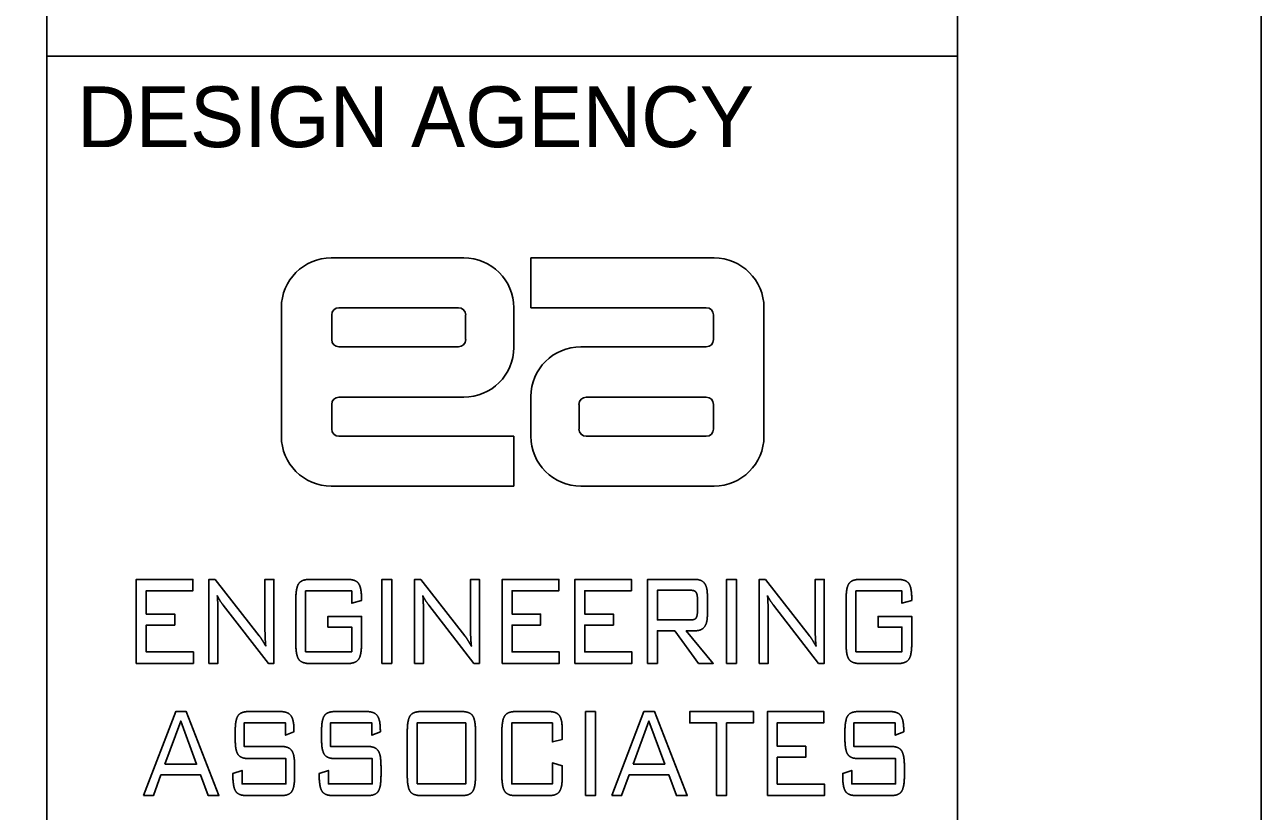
# Model space of a CAD drawing. Extents: x 0 to 34, y 0 to 22.
# Drawn here: x 31.964 to 34, y 3.757 to 5.052 of the extents above; entities that cross this region are included whole.
import ezdxf

# ---------------------------------------------------------------- set-up
doc = ezdxf.new("R2010")
doc.units = 0
for name, color, linetype in [('SH_Border', 7, 'Continuous'), ('SH_Cut_Line', 7, 'Continuous'), ('SH_Data', 7, 'Continuous'), ('TX_X_20', 7, 'Continuous')]:
    doc.layers.add(name, color=color, linetype=linetype)

msp = doc.modelspace()

# ---------------------------------------------------------------- linework, layer by layer
at = {"layer": 'SH_Border'}
for p, q in [((32, 0.5), (32, 21.5)), ((32, 5), (33.5, 5))]:
    msp.add_line(p, q, dxfattribs=at)
msp.add_lwpolyline([(1.5, 21.5), (33.5, 21.5), (33.5, 0.5), (1.5, 0.5)], close=True, dxfattribs=at)
at = {"layer": 'SH_Cut_Line'}
msp.add_lwpolyline([(0, 0), (34, 0), (34, 22), (0, 22)], close=True, dxfattribs=at)
at = {"layer": 'SH_Data'}
msp.add_line((32.75, 4), (32.75, 4), dxfattribs=at)
at = {"layer": 'TX_X_20'}
for p, q in [((32.6869, 4.6677), (32.4684, 4.6677)), ((32.4684, 4.6677), (32.6869, 4.6677)), ((32.7974, 4.6677), (33.0989, 4.6677)), ((32.7974, 4.5856), (32.7974, 4.6677)), ((32.3863, 4.5856), (32.3863, 4.3741)), ((32.3863, 4.3741), (32.3863, 4.5856)), ((32.4812, 4.5856), (32.678, 4.5856)), ((32.678, 4.5856), (32.4812, 4.5856)), ((32.7689, 4.5204), (32.7689, 4.5856)), ((32.7689, 4.5856), (32.7689, 4.5204)), ((33.086, 4.5856), (32.7974, 4.5856)), ((33.1809, 4.3741), (33.1809, 4.5856)), ((33.1809, 4.5856), (33.1809, 4.3741)), ((32.4694, 4.5332), (32.4694, 4.5738)), ((32.4694, 4.5738), (32.4694, 4.5332)), ((32.6898, 4.5738), (32.6898, 4.5332)), ((32.6898, 4.5332), (32.6898, 4.5738)), ((33.0979, 4.5738), (33.0979, 4.5332)), ((33.0979, 4.5332), (33.0979, 4.5738)), ((32.678, 4.5214), (32.4812, 4.5214)), ((32.4812, 4.5214), (32.678, 4.5214)), ((33.086, 4.5214), (32.8794, 4.5214)), ((32.8794, 4.5214), (33.086, 4.5214)), ((32.7974, 4.4393), (32.7974, 4.3741)), ((32.7974, 4.3741), (32.7974, 4.4393)), ((32.4694, 4.3859), (32.4694, 4.4265)), ((32.4694, 4.4265), (32.4694, 4.3859)), ((32.4812, 4.4383), (32.6869, 4.4383)), ((32.6869, 4.4383), (32.4812, 4.4383)), ((32.8765, 4.3859), (32.8765, 4.4265)), ((32.8765, 4.4265), (32.8765, 4.3859)), ((32.8883, 4.4383), (33.086, 4.4383)), ((33.086, 4.4383), (32.8883, 4.4383)), ((33.0979, 4.4265), (33.0979, 4.3859)), ((33.0979, 4.3859), (33.0979, 4.4265)), ((32.4812, 4.3741), (32.7689, 4.3741)), ((32.7689, 4.3741), (32.7689, 4.292)), ((33.086, 4.3741), (32.8883, 4.3741)), ((32.8883, 4.3741), (33.086, 4.3741)), ((32.7689, 4.292), (32.4684, 4.292)), ((32.8794, 4.292), (33.0989, 4.292)), ((33.0989, 4.292), (32.8794, 4.292)), ((32.4329, 4.1384), (32.4956, 4.1384)), ((33.339, 4.1384), (33.4017, 4.1384)), ((32.4101, 4.0328), (32.4101, 4.1057)), ((33.0715, 4.1062), (33.0715, 4.086)), ((33.0879, 4.0806), (33.0879, 4.1116)), ((33.3163, 4.0328), (33.3163, 4.1057)), ((32.4956, 4), (32.4329, 4)), ((33.4017, 4), (33.339, 4)), ((32.3328, 3.9209), (32.3843, 3.9209)), ((32.475, 3.9209), (32.5265, 3.9209)), ((32.6834, 3.9209), (32.6165, 3.9209)), ((32.7722, 3.9209), (32.8264, 3.9209)), ((33.3369, 3.9209), (33.3884, 3.9209)), ((32.3103, 3.8761), (32.3103, 3.8882)), ((32.4525, 3.8761), (32.4525, 3.8882)), ((32.5937, 3.8882), (32.5937, 3.8152)), ((32.706, 3.8152), (32.706, 3.8882)), ((32.7495, 3.8152), (32.7495, 3.8882)), ((33.3144, 3.8761), (33.3144, 3.8882)), ((32.4082, 3.8308), (32.4082, 3.8152)), ((32.5504, 3.8308), (32.5504, 3.8152)), ((33.4123, 3.8308), (33.4123, 3.8152)), ((32.3857, 3.7825), (32.3293, 3.7825)), ((32.5279, 3.7825), (32.4715, 3.7825)), ((32.6165, 3.7825), (32.6834, 3.7825)), ((32.8264, 3.7825), (32.7722, 3.7825)), ((33.3898, 3.7825), (33.3334, 3.7825))]:
    msp.add_line(p, q, dxfattribs=at)
for points in [[(33.0989, 4.6677), (32.7974, 4.6677), (32.7974, 4.5856), (33.086, 4.5856)], [(32.4684, 4.292), (32.7689, 4.292), (32.7689, 4.3741), (32.4812, 4.3741)], [(32.2819, 4.0816), (32.2819, 4), (32.2671, 4), (32.2671, 4.1384), (32.2773, 4.1384), (32.3497, 4.0458)], [(32.3593, 4.0625), (32.3593, 4.1384), (32.3741, 4.1384), (32.3741, 4), (32.365, 4), (32.2906, 4.0962)], [(32.6204, 4.0816), (32.6204, 4), (32.6056, 4), (32.6056, 4.1384), (32.6158, 4.1384), (32.6883, 4.0458)], [(32.6978, 4.0625), (32.6978, 4.1384), (32.7126, 4.1384), (32.7126, 4), (32.7035, 4), (32.6291, 4.0962)], [(33.0674, 4.1384), (32.9893, 4.1384), (32.9893, 4), (33.0056, 4), (33.0056, 4.0539), (33.034, 4.0539), (33.0734, 4), (33.0974, 4), (33.0532, 4.0539), (33.0674, 4.0539)], [(33.188, 4.0816), (33.188, 4), (33.1732, 4), (33.1732, 4.1384), (33.1834, 4.1384), (33.2559, 4.0458)], [(33.2654, 4.0625), (33.2654, 4.1384), (33.2802, 4.1384), (33.2802, 4), (33.2711, 4), (33.1967, 4.0962)], [(32.5183, 4.1072), (32.5183, 4.1038), (32.5022, 4.0992), (32.5022, 4.1196), (32.4263, 4.1196), (32.4263, 4.0192), (32.5022, 4.0192), (32.5022, 4.0599), (32.463, 4.0599), (32.463, 4.0775), (32.5183, 4.0775), (32.5183, 4.0328)], [(33.061, 4.0718), (33.0056, 4.0718), (33.0056, 4.1205), (33.061, 4.1205)], [(33.4244, 4.1072), (33.4244, 4.1038), (33.4083, 4.0992), (33.4083, 4.1196), (33.3324, 4.1196), (33.3324, 4.0192), (33.4083, 4.0192), (33.4083, 4.0599), (33.3691, 4.0599), (33.3691, 4.0775), (33.4244, 4.0775), (33.4244, 4.0328)], [(32.407, 3.8905), (32.407, 3.8877), (32.3932, 3.882), (32.3932, 3.9021), (32.3248, 3.9021), (32.3248, 3.8635), (32.3857, 3.8635)], [(32.5493, 3.8905), (32.5493, 3.8877), (32.5354, 3.882), (32.5354, 3.9021), (32.467, 3.9021), (32.467, 3.8635), (32.5279, 3.8635)], [(32.849, 3.8882), (32.849, 3.8751), (32.8327, 3.8708), (32.8327, 3.9021), (32.7656, 3.9021), (32.7656, 3.8018), (32.8327, 3.8018), (32.8327, 3.8364), (32.849, 3.8316), (32.849, 3.8152)], [(33.4112, 3.8905), (33.4112, 3.8877), (33.3973, 3.882), (33.3973, 3.9021), (33.3289, 3.9021), (33.3289, 3.8635), (33.3898, 3.8635)], [(32.3065, 3.8152), (32.3065, 3.819), (32.3215, 3.824), (32.3215, 3.8018), (32.3937, 3.8018), (32.3937, 3.8434), (32.3328, 3.8434)], [(32.4487, 3.8152), (32.4487, 3.819), (32.4637, 3.824), (32.4637, 3.8018), (32.5359, 3.8018), (32.5359, 3.8434), (32.475, 3.8434)], [(33.3107, 3.8152), (33.3107, 3.819), (33.3257, 3.824), (33.3257, 3.8018), (33.3978, 3.8018), (33.3978, 3.8434), (33.3369, 3.8434)]]:
    msp.add_lwpolyline(points, dxfattribs=at)
for points in [[(32.1474, 4), (32.1474, 4.1384), (32.2407, 4.1384), (32.2407, 4.1198), (32.1637, 4.1198), (32.1637, 4.0813), (32.2108, 4.0813), (32.2108, 4.0631), (32.1637, 4.0631), (32.1637, 4.019), (32.2414, 4.019), (32.2414, 4)], [(32.552, 4), (32.552, 4.1384), (32.5682, 4.1384), (32.5682, 4)], [(32.75, 4), (32.75, 4.1384), (32.8433, 4.1384), (32.8433, 4.1198), (32.7662, 4.1198), (32.7662, 4.0813), (32.8133, 4.0813), (32.8133, 4.0631), (32.7662, 4.0631), (32.7662, 4.019), (32.844, 4.019), (32.844, 4)], [(32.8697, 4), (32.8697, 4.1384), (32.9629, 4.1384), (32.9629, 4.1198), (32.8859, 4.1198), (32.8859, 4.0813), (32.933, 4.0813), (32.933, 4.0631), (32.8859, 4.0631), (32.8859, 4.019), (32.9637, 4.019), (32.9637, 4)], [(33.1196, 4), (33.1196, 4.1384), (33.1358, 4.1384), (33.1358, 4)], [(32.1595, 3.7825), (32.1755, 3.7825), (32.1879, 3.8166), (32.2534, 3.8166), (32.2658, 3.7825), (32.2836, 3.7825), (32.2297, 3.9209), (32.2124, 3.9209)], [(32.8873, 3.7825), (32.8873, 3.9209), (32.9036, 3.9209), (32.9036, 3.7825)], [(32.9305, 3.7825), (32.9465, 3.7825), (32.9589, 3.8166), (33.0244, 3.8166), (33.0368, 3.7825), (33.0546, 3.7825), (33.0008, 3.9209), (32.9834, 3.9209)], [(33.1192, 3.9021), (33.1192, 3.7825), (33.103, 3.7825), (33.103, 3.9021), (33.0588, 3.9021), (33.0588, 3.9209), (33.1636, 3.9209), (33.1636, 3.9021)], [(33.1866, 3.7825), (33.1866, 3.9209), (33.2798, 3.9209), (33.2798, 3.9024), (33.2028, 3.9024), (33.2028, 3.8639), (33.2499, 3.8639), (33.2499, 3.8456), (33.2028, 3.8456), (33.2028, 3.8015), (33.2806, 3.8015), (33.2806, 3.7825)], [(32.1946, 3.8342), (32.2207, 3.9051), (32.2468, 3.8342)], [(32.6099, 3.8018), (32.6099, 3.9021), (32.69, 3.9021), (32.69, 3.8018)], [(32.9657, 3.8342), (32.9917, 3.9051), (33.0178, 3.8342)]]:
    msp.add_lwpolyline(points, close=True, dxfattribs=at)
for centre, radius, start, end in [((32.4684, 4.5856), 0.0821, 90, 180), ((32.4684, 4.5856), 0.0821, 90, 180), ((32.6869, 4.5856), 0.0821, 0, 90), ((32.6869, 4.5856), 0.0821, 0, 90), ((33.0989, 4.5856), 0.0821, 0, 90), ((33.0989, 4.5856), 0.0821, 0, 90), ((32.4812, 4.5738), 0.0119, 90, 180), ((32.4812, 4.5738), 0.0119, 90, 180), ((32.678, 4.5738), 0.0119, 0, 90), ((32.678, 4.5738), 0.0119, 0, 90), ((33.086, 4.5738), 0.0119, 0, 90), ((33.086, 4.5738), 0.0119, 0, 90), ((32.4812, 4.5332), 0.0119, 180, 270), ((32.4812, 4.5332), 0.0119, 180, 270), ((32.678, 4.5332), 0.0119, 270, 0), ((32.678, 4.5332), 0.0119, 270, 0), ((32.8794, 4.4393), 0.0821, 90, 180), ((32.8794, 4.4393), 0.0821, 90, 180), ((33.086, 4.5332), 0.0119, 270, 0), ((33.086, 4.5332), 0.0119, 270, 0), ((32.6869, 4.5204), 0.0821, 270, 360), ((32.6869, 4.5204), 0.0821, 270, 360), ((32.4812, 4.4265), 0.0119, 90, 180), ((32.4812, 4.4265), 0.0119, 90, 180), ((32.8883, 4.4265), 0.0119, 90, 180), ((32.8883, 4.4265), 0.0119, 90, 180), ((33.086, 4.4265), 0.0119, 0, 90), ((33.086, 4.4265), 0.0119, 0, 90), ((32.4812, 4.3859), 0.0119, 180, 270), ((32.4812, 4.3859), 0.0119, 180, 270), ((32.8883, 4.3859), 0.0119, 180, 270), ((32.8883, 4.3859), 0.0119, 180, 270), ((33.086, 4.3859), 0.0119, 270, 0), ((33.086, 4.3859), 0.0119, 270, 0), ((32.4684, 4.3741), 0.0821, 180, 270), ((32.4684, 4.3741), 0.0821, 180, 270), ((32.8794, 4.3741), 0.0821, 180, 270), ((32.8794, 4.3741), 0.0821, 180, 270), ((33.0989, 4.3741), 0.0821, 270, 360), ((33.0989, 4.3741), 0.0821, 270, 360)]:
    msp.add_arc(centre, radius, start, end, dxfattribs=at)
for points in [[(32.4149, 4.1315), (32.4196, 4.1384), (32.4329, 4.1384)], [(32.4956, 4.1384), (32.5086, 4.1384), (32.5134, 4.1317)], [(33.0831, 4.1321), (33.0783, 4.1384), (33.0674, 4.1384)], [(33.321, 4.1315), (33.3257, 4.1384), (33.339, 4.1384)], [(33.4017, 4.1384), (33.4147, 4.1384), (33.4196, 4.1317)], [(32.4101, 4.1057), (32.4101, 4.1245), (32.4149, 4.1315)], [(32.5134, 4.1317), (32.5183, 4.1249), (32.5183, 4.1072)], [(33.061, 4.1205), (33.067, 4.1205), (33.0692, 4.1173)], [(33.0692, 4.1173), (33.0715, 4.1141), (33.0715, 4.1062)], [(33.0879, 4.1116), (33.0879, 4.1257), (33.0831, 4.1321)], [(33.3163, 4.1057), (33.3163, 4.1245), (33.321, 4.1315)], [(33.4196, 4.1317), (33.4244, 4.1249), (33.4244, 4.1072)], [(32.2889, 4.0983), (32.2834, 4.1054), (32.2808, 4.1118)], [(32.2808, 4.1118), (32.2813, 4.1055), (32.2816, 4.0984)], [(32.2816, 4.0984), (32.2819, 4.0913), (32.2819, 4.0816)], [(32.2906, 4.0962), (32.29, 4.0969), (32.2889, 4.0983)], [(32.6275, 4.0983), (32.622, 4.1054), (32.6193, 4.1118)], [(32.6193, 4.1118), (32.6199, 4.1055), (32.6201, 4.0984)], [(32.6201, 4.0984), (32.6204, 4.0913), (32.6204, 4.0816)], [(32.6291, 4.0962), (32.6286, 4.0969), (32.6275, 4.0983)], [(33.1951, 4.0983), (33.1896, 4.1054), (33.1869, 4.1118)], [(33.1869, 4.1118), (33.1875, 4.1055), (33.1877, 4.0984)], [(33.1877, 4.0984), (33.188, 4.0913), (33.188, 4.0816)], [(33.1967, 4.0962), (33.1962, 4.0969), (33.1951, 4.0983)], [(33.0693, 4.0749), (33.0671, 4.0718), (33.061, 4.0718)], [(33.0715, 4.086), (33.0715, 4.0781), (33.0693, 4.0749)], [(33.0831, 4.0603), (33.0879, 4.0666), (33.0879, 4.0806)], [(32.3596, 4.0424), (32.3593, 4.0496), (32.3593, 4.0625)], [(32.6982, 4.0424), (32.6978, 4.0496), (32.6978, 4.0625)], [(33.0674, 4.0539), (33.0783, 4.0539), (33.0831, 4.0603)], [(33.2658, 4.0424), (33.2654, 4.0496), (33.2654, 4.0625)], [(32.3497, 4.0458), (32.3522, 4.0427), (32.355, 4.0382)], [(32.355, 4.0382), (32.3578, 4.0338), (32.3607, 4.0284)], [(32.3607, 4.0284), (32.36, 4.0351), (32.3596, 4.0424)], [(32.4149, 4.0069), (32.4101, 4.0139), (32.4101, 4.0328)], [(32.5183, 4.0328), (32.5183, 4.0138), (32.5135, 4.0069)], [(32.6883, 4.0458), (32.6907, 4.0427), (32.6935, 4.0382)], [(32.6935, 4.0382), (32.6963, 4.0338), (32.6993, 4.0284)], [(32.6993, 4.0284), (32.6985, 4.0351), (32.6982, 4.0424)], [(33.2559, 4.0458), (33.2583, 4.0427), (33.2611, 4.0382)], [(33.2611, 4.0382), (33.2639, 4.0338), (33.2669, 4.0284)], [(33.2669, 4.0284), (33.2661, 4.0351), (33.2658, 4.0424)], [(33.321, 4.0069), (33.3163, 4.0139), (33.3163, 4.0328)], [(33.4244, 4.0328), (33.4244, 4.0138), (33.4197, 4.0069)], [(32.4329, 4), (32.4196, 4), (32.4149, 4.0069)], [(32.5135, 4.0069), (32.5088, 4), (32.4956, 4)], [(33.339, 4), (33.3257, 4), (33.321, 4.0069)], [(33.4197, 4.0069), (33.4149, 4), (33.4017, 4)], [(32.3103, 3.8882), (32.3103, 3.9072), (32.3149, 3.914)], [(32.3149, 3.914), (32.3196, 3.9209), (32.3328, 3.9209)], [(32.3843, 3.9209), (32.3972, 3.9209), (32.4021, 3.9142)], [(32.4021, 3.9142), (32.407, 3.9074), (32.407, 3.8905)], [(32.4525, 3.8882), (32.4525, 3.9072), (32.4571, 3.914)], [(32.4571, 3.914), (32.4618, 3.9209), (32.475, 3.9209)], [(32.5265, 3.9209), (32.5394, 3.9209), (32.5443, 3.9142)], [(32.5443, 3.9142), (32.5493, 3.9074), (32.5493, 3.8905)], [(32.5984, 3.914), (32.5937, 3.907), (32.5937, 3.8882)], [(32.6165, 3.9209), (32.6032, 3.9209), (32.5984, 3.914)], [(32.7013, 3.914), (32.6965, 3.9209), (32.6834, 3.9209)], [(32.706, 3.8882), (32.706, 3.9072), (32.7013, 3.914)], [(32.7495, 3.8882), (32.7495, 3.9072), (32.7543, 3.914)], [(32.7543, 3.914), (32.759, 3.9209), (32.7722, 3.9209)], [(32.8264, 3.9209), (32.8396, 3.9209), (32.8443, 3.9141)], [(32.8443, 3.9141), (32.849, 3.9073), (32.849, 3.8882)], [(33.3144, 3.8882), (33.3144, 3.9072), (33.3191, 3.914)], [(33.3191, 3.914), (33.3237, 3.9209), (33.3369, 3.9209)], [(33.3884, 3.9209), (33.4014, 3.9209), (33.4063, 3.9142)], [(33.4063, 3.9142), (33.4112, 3.9074), (33.4112, 3.8905)], [(32.3149, 3.8503), (32.3103, 3.8571), (32.3103, 3.8761)], [(32.4571, 3.8503), (32.4525, 3.8571), (32.4525, 3.8761)], [(33.3191, 3.8503), (33.3144, 3.8571), (33.3144, 3.8761)], [(32.3328, 3.8434), (32.3196, 3.8434), (32.3149, 3.8503)], [(32.3857, 3.8635), (32.3986, 3.8635), (32.4034, 3.8566)], [(32.4034, 3.8566), (32.4082, 3.8498), (32.4082, 3.8308)], [(32.475, 3.8434), (32.4618, 3.8434), (32.4571, 3.8503)], [(32.5279, 3.8635), (32.5408, 3.8635), (32.5456, 3.8566)], [(32.5456, 3.8566), (32.5504, 3.8498), (32.5504, 3.8308)], [(33.3369, 3.8434), (33.3237, 3.8434), (33.3191, 3.8503)], [(33.3898, 3.8635), (33.4028, 3.8635), (33.4075, 3.8566)], [(33.4075, 3.8566), (33.4123, 3.8498), (33.4123, 3.8308)], [(32.3113, 3.7894), (32.3065, 3.7963), (32.3065, 3.8152)], [(32.4082, 3.8152), (32.4082, 3.7961), (32.4035, 3.7893)], [(32.4535, 3.7894), (32.4487, 3.7963), (32.4487, 3.8152)], [(32.5504, 3.8152), (32.5504, 3.7961), (32.5457, 3.7893)], [(32.5937, 3.8152), (32.5937, 3.7964), (32.5984, 3.7895)], [(32.7013, 3.7893), (32.706, 3.7961), (32.706, 3.8152)], [(32.7543, 3.7894), (32.7495, 3.7963), (32.7495, 3.8152)], [(32.849, 3.8152), (32.849, 3.7961), (32.8443, 3.7893)], [(33.3154, 3.7894), (33.3107, 3.7963), (33.3107, 3.8152)], [(33.4123, 3.8152), (33.4123, 3.7961), (33.4076, 3.7893)], [(32.3293, 3.7825), (32.3161, 3.7825), (32.3113, 3.7894)], [(32.4035, 3.7893), (32.3988, 3.7825), (32.3857, 3.7825)], [(32.4715, 3.7825), (32.4583, 3.7825), (32.4535, 3.7894)], [(32.5457, 3.7893), (32.541, 3.7825), (32.5279, 3.7825)], [(32.5984, 3.7895), (32.6032, 3.7825), (32.6165, 3.7825)], [(32.6834, 3.7825), (32.6965, 3.7825), (32.7013, 3.7893)], [(32.7722, 3.7825), (32.759, 3.7825), (32.7543, 3.7894)], [(32.8443, 3.7893), (32.8396, 3.7825), (32.8264, 3.7825)], [(33.3334, 3.7825), (33.3202, 3.7825), (33.3154, 3.7894)], [(33.4076, 3.7893), (33.4029, 3.7825), (33.3898, 3.7825)]]:
    msp.add_open_spline(points, degree=2, dxfattribs=at)

# ---------------------------------------------------------------- texts
at = {"layer": 'SH_Data'}
msp.add_text('DESIGN AGENCY', height=0.1, dxfattribs=at).set_placement((32.05, 4.85))

doc.saveas('drawing.dxf')
